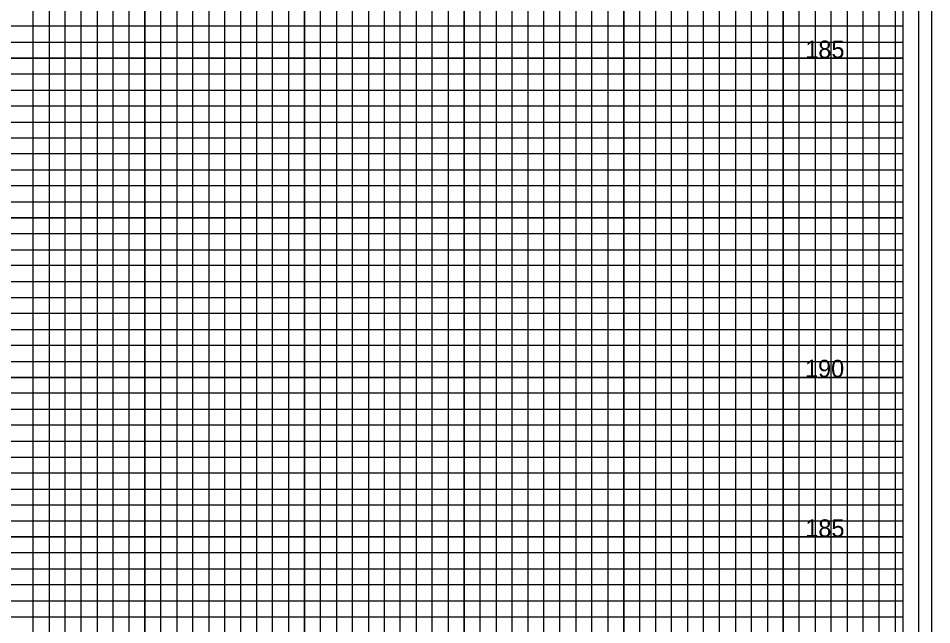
# Model space of a CAD drawing. Extents: x -4 to 103, y -2 to 138.
# Drawn here: x 74.78 to 103.4, y 103.08 to 122.08 of the extents above; entities that cross this region are included whole.
import ezdxf

# ---------------------------------------------------------------- set-up
doc = ezdxf.new("R2010")
doc.units = 0
for name, color, linetype in [('Old_Level_10', 7, 'Continuous'), ('Old_Level_4', 7, 'Continuous'), ('Old_Level_5', 7, 'Continuous'), ('Old_Level_8', 7, 'Continuous'), ('Prop Dimension', 7, 'Continuous'), ('Prop XS Finish Grade', 7, 'Continuous'), ('Prop XS SE Text', 7, 'Continuous')]:
    doc.layers.add(name, color=color, linetype=linetype)

msp = doc.modelspace()

# ---------------------------------------------------------------- linework, layer by layer
at = {"layer": 'Old_Level_10'}
for p, q in [((91.25, 70.825), (91.25, 134.25)), ((93.75, 70.825), (93.75, 134.25)), ((96.25, 70.825), (96.25, 134.25)), ((98.75, 70.825), (98.75, 134.25)), ((101.25, 70.825), (101.25, 134.25)), ((76.25, 70.825), (76.25, 132.825)), ((78.75, 70.825), (78.75, 132.825)), ((81.25, 70.825), (81.25, 132.825)), ((83.75, 70.825), (83.75, 132.825)), ((86.25, 70.825), (86.25, 132.825)), ((88.75, 70.825), (88.75, 132.825)), ((0, 120.825), (102.5, 120.825)), ((0, 118.325), (102.5, 118.325)), ((0, 115.825), (102.5, 115.825)), ((0, 113.325), (102.5, 113.325)), ((0, 110.825), (102.5, 110.825)), ((0, 108.325), (102.5, 108.325)), ((0, 105.825), (102.5, 105.825)), ((0, 103.325), (102.5, 103.325))]:
    msp.add_line(p, q, dxfattribs=at)
at = {"layer": 'Old_Level_4'}
msp.add_lwpolyline([(103, 136.825), (-2.8, 136.825), (-2.8, 69.825), (103, 69.825)], close=True, dxfattribs=at)
at = {"layer": 'Old_Level_5'}
msp.add_lwpolyline([(103.4, 138.225), (-3.5, 138.225), (-3.5, 68.4), (103.4, 68.4)], close=True, dxfattribs=at)
at = {"layer": 'Old_Level_8'}
for points in [[(91.25, 70.825), (91.25, 134.25), (93.75, 134.25), (93.75, 70.825)], [(96.25, 70.825), (96.25, 134.25), (98.75, 134.25), (98.75, 70.825)], [(101.25, 70.825), (101.25, 134.25)], [(76.25, 70.825), (76.25, 132.825), (78.75, 132.825), (78.75, 70.825)], [(81.25, 70.825), (81.25, 132.825), (83.75, 132.825), (83.75, 70.825)], [(86.25, 70.825), (86.25, 132.825), (88.75, 132.825), (88.75, 70.825)], [(0, 118.325), (102.5, 118.325), (102.5, 120.825), (0, 120.825)], [(0, 113.325), (102.5, 113.325), (102.5, 115.825), (0, 115.825)], [(0, 108.325), (102.5, 108.325), (102.5, 110.825), (0, 110.825)], [(0, 103.325), (102.5, 103.325), (102.5, 105.825), (0, 105.825)]]:
    msp.add_lwpolyline(points, dxfattribs=at)
at = {"layer": 'Prop Dimension'}
for points in [[(90.25, 70.825), (90.25, 134.25), (90.75, 134.25), (90.75, 70.825)], [(91.75, 70.825), (91.75, 134.25), (92.25, 134.25), (92.25, 70.825)], [(92.75, 70.825), (92.75, 134.25), (93.25, 134.25), (93.25, 70.825)], [(94.25, 70.825), (94.25, 134.25), (94.75, 134.25), (94.75, 70.825)], [(95.25, 70.825), (95.25, 134.25), (95.75, 134.25), (95.75, 70.825)], [(96.75, 70.825), (96.75, 134.25), (97.25, 134.25), (97.25, 70.825)], [(97.75, 70.825), (97.75, 134.25), (98.25, 134.25), (98.25, 70.825)], [(99.25, 70.825), (99.25, 134.25), (99.75, 134.25), (99.75, 70.825)], [(100.25, 70.825), (100.25, 134.25)], [(100.25, 134.25), (100.75, 134.25), (100.75, 70.825), (101.75, 70.825), (101.75, 134.25), (102.25, 134.25), (102.25, 70.825)], [(75.25, 70.825), (75.25, 132.825), (75.75, 132.825), (75.75, 70.825)], [(76.75, 70.825), (76.75, 132.825), (77.25, 132.825), (77.25, 70.825)], [(77.75, 70.825), (77.75, 132.825), (78.25, 132.825), (78.25, 70.825)], [(79.25, 70.825), (79.25, 132.825), (79.75, 132.825), (79.75, 70.825)], [(80.25, 70.825), (80.25, 132.825), (80.75, 132.825), (80.75, 70.825)], [(81.75, 70.825), (81.75, 132.825), (82.25, 132.825), (82.25, 70.825)], [(82.75, 70.825), (82.75, 132.825), (83.25, 132.825), (83.25, 70.825)], [(84.25, 70.825), (84.25, 132.825), (84.75, 132.825), (84.75, 70.825)], [(85.25, 70.825), (85.25, 132.825), (85.75, 132.825), (85.75, 70.825)], [(86.75, 70.825), (86.75, 132.825), (87.25, 132.825), (87.25, 70.825)], [(87.75, 70.825), (87.75, 132.825), (88.25, 132.825), (88.25, 70.825)], [(89.25, 70.825), (89.25, 132.825), (89.75, 132.825), (89.75, 70.825)], [(0, 121.325), (102.5, 121.325), (102.5, 121.825), (0, 121.825)], [(0, 119.825), (102.5, 119.825), (102.5, 120.325), (0, 120.325)], [(0, 118.825), (102.5, 118.825), (102.5, 119.325), (0, 119.325)], [(0, 117.325), (102.5, 117.325), (102.5, 117.825), (0, 117.825)], [(0, 116.325), (102.5, 116.325), (102.5, 116.825), (0, 116.825)], [(0, 114.825), (102.5, 114.825), (102.5, 115.325), (0, 115.325)], [(0, 113.825), (102.5, 113.825), (102.5, 114.325), (0, 114.325)], [(0, 112.325), (102.5, 112.325), (102.5, 112.825), (0, 112.825)], [(0, 111.325), (102.5, 111.325), (102.5, 111.825), (0, 111.825)], [(0, 109.825), (102.5, 109.825), (102.5, 110.325), (0, 110.325)], [(0, 108.825), (102.5, 108.825), (102.5, 109.325), (0, 109.325)], [(0, 107.325), (102.5, 107.325), (102.5, 107.825), (0, 107.825)], [(0, 106.325), (102.5, 106.325), (102.5, 106.825), (0, 106.825)], [(0, 104.825), (102.5, 104.825), (102.5, 105.325), (0, 105.325)], [(0, 103.825), (102.5, 103.825), (102.5, 104.325), (0, 104.325)]]:
    msp.add_lwpolyline(points, dxfattribs=at)
at = {"layer": 'Prop XS SE Text'}
msp.add_lwpolyline([(102.5, 135.825), (0, 135.825), (0, 70.825), (102.5, 70.825)], close=True, dxfattribs=at)

# ---------------------------------------------------------------- texts
at = {"layer": 'Prop XS Finish Grade'}
for s, p in [('185', (99.4383, 120.825)), ('190', (99.4296, 110.825)), ('185', (99.4383, 105.825))]:
    msp.add_text(s, height=0.55, dxfattribs=at).set_placement(p)

doc.saveas('drawing.dxf')
